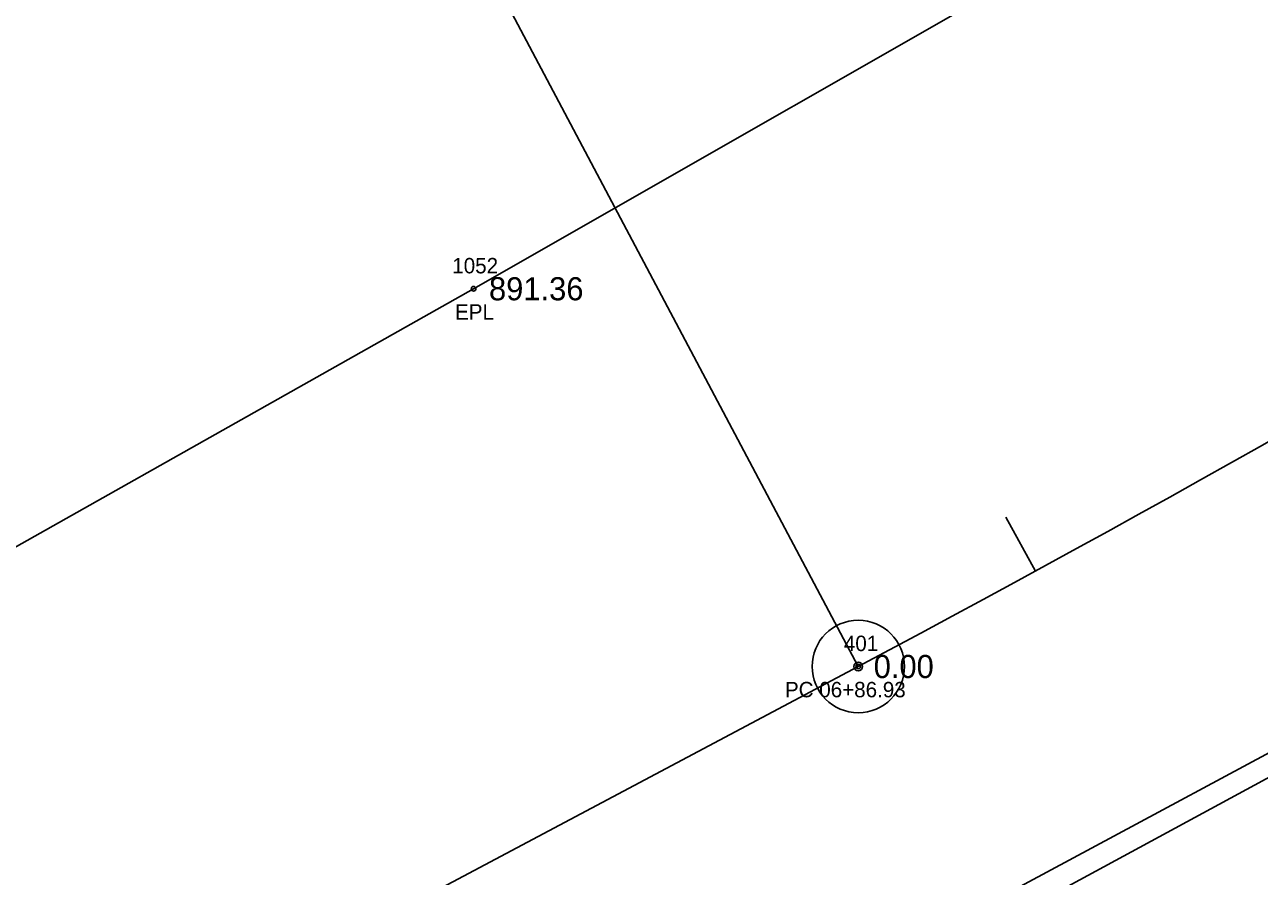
# Model space of a CAD drawing. Extents: x 1622501 to 1626664, y 1117816 to 1121579.
# Drawn here: x 1623315.6 to 1623395.8, y 1118720.5 to 1118775.8 of the extents above; entities that cross this region are included whole.
import ezdxf

# ---------------------------------------------------------------- set-up
doc = ezdxf.new("R2010")
doc.units = 0
for name, color, linetype in [('RD_EX_Conc', 7, 'Continuous'), ('RD_EX_Road', 7, 'Continuous'), ('RD_EX_Road_txCode', 7, 'Continuous'), ('RD_EX_TX_Road_ELEV', 7, 'Continuous'), ('RD_HC_Cl', 7, 'Continuous'), ('RD_HC_Data', 7, 'Continuous'), ('RD_HC_Data_Tic', 7, 'Continuous'), ('RD_HC_Survey_ELEV', 7, 'Continuous'), ('RD_HC_txCode', 7, 'Continuous'), ('RD_SMD_Locator', 7, 'Continuous')]:
    doc.layers.add(name, color=color, linetype=linetype)

msp = doc.modelspace()

# ---------------------------------------------------------------- linework, layer by layer
at = {"layer": 'RD_EX_Conc'}
msp.add_lwpolyline([(1623283.761, 1118664.167), (1623326.745, 1118688.794), (1623370.205, 1118712.758), (1623413.974, 1118736.474), (1623457.083, 1118761.617), (1623498.83, 1118789.052), (1623539.225, 1118818.399), (1623578.605, 1118849.246), (1623610.287, 1118876.06), (1623617.2, 1118880.675), (1623627.78, 1118883.825), (1623633.909, 1118884.567), (1623640.773, 1118884.032), (1623649.389, 1118881.534), (1623656.998, 1118877.662), (1623663.674, 1118871.908), (1623688.617, 1118845.058), (1623694.116, 1118836.37)], dxfattribs=at)
at = {"layer": 'RD_EX_Road'}
for points in [[(1623260.544, 1118725.947), (1623288.21, 1118727.494), (1623301.478, 1118734.285), (1623344.734, 1118758.666), (1623386.195, 1118782.361), (1623428.983, 1118807.994), (1623470.075, 1118833.282), (1623514.573, 1118855.089), (1623531.484, 1118864.83), (1623546.898, 1118876.996), (1623552.555, 1118884.256), (1623552.914, 1118883.943), (1623553.833, 1118883.161), (1623571.535, 1118911.829), (1623572.649, 1118913.698), (1623580.364, 1118928.717), (1623584.235, 1118943.716), (1623583.027, 1118956.881), (1623577.503, 1118968.655), (1623574.751, 1118973.142), (1623569.429, 1118983.782), (1623564.782, 1119000.817), (1623565.613, 1119022.949), (1623574.197, 1119045.059)], [(1623282.988, 1118665.294), (1623326.108, 1118690.168), (1623369.47, 1118714.084), (1623413.312, 1118737.635), (1623456.355, 1118762.797), (1623498.01, 1118790.21), (1623538.412, 1118819.484), (1623577.719, 1118850.337), (1623609.415, 1118877.294), (1623616.689, 1118881.904), (1623627.606, 1118885.26), (1623634.056, 1118885.78), (1623640.822, 1118885.362), (1623649.781, 1118882.397), (1623657.444, 1118878.352), (1623664.357, 1118872.554), (1623689.274, 1118845.674), (1623694.989, 1118836.791)]]:
    msp.add_lwpolyline(points, dxfattribs=at)
at = {"layer": 'RD_HC_Cl'}
msp.add_line((1623239.038, 1118664.809), (1623369.718, 1118734.144), dxfattribs=at)
msp.add_arc((1622842.024, 1119728.712), 1125.889, 297.949368, 312.927633, dxfattribs=at)
at = {"layer": 'RD_HC_Data'}
msp.add_line((1623369.718, 1118734.144), (1623317.207, 1118833.114), dxfattribs=at)
for radius in [3, 0.282]:
    msp.add_circle((1623369.718, 1118734.144), radius, dxfattribs=at)
at = {"layer": 'RD_HC_Data_Tic'}
msp.add_line((1623381.224, 1118740.335), (1623379.308, 1118743.846), dxfattribs=at)
at = {"layer": 'RD_SMD_Locator'}
for centre in [(1623344.734, 1118758.666), (1623369.718, 1118734.144)]:
    msp.add_circle(centre, 0.15, dxfattribs=at)

# ---------------------------------------------------------------- texts
at = {"layer": 'RD_EX_Road_txCode'}
for s, p in [('1052', (1623343.348, 1118759.666)), ('EPL', (1623343.529, 1118756.666))]:
    msp.add_text(s, height=1, dxfattribs=at).set_placement(p)
at = {"layer": 'RD_EX_TX_Road_ELEV'}
msp.add_text('891.36', height=1.5, dxfattribs=at).set_placement((1623345.734, 1118757.916))
at = {"layer": 'RD_HC_Survey_ELEV'}
msp.add_text('0.00', height=1.5, dxfattribs=at).set_placement((1623370.718, 1118733.394))
at = {"layer": 'RD_HC_txCode'}
for s, p in [('401', (1623368.781, 1118735.144)), ('PC 06+86.93', (1623364.954, 1118732.144))]:
    msp.add_text(s, height=1, dxfattribs=at).set_placement(p)

doc.saveas('drawing.dxf')
